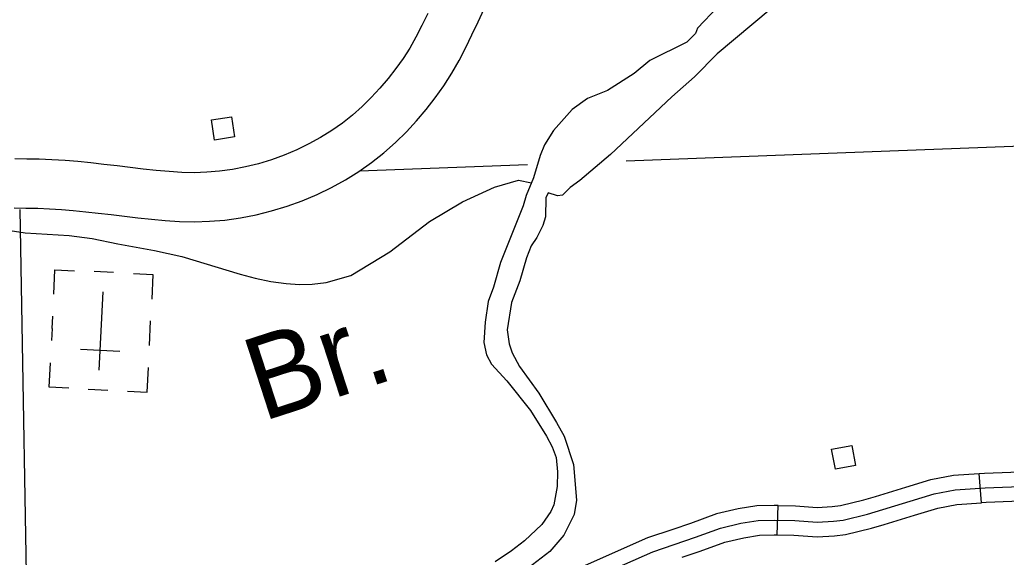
# Model space of a CAD drawing. Extents: x 1370130 to 1380143, y 377636 to 380256.
# Drawn here: x 1377546.5 to 1377687.4, y 378956.8 to 379033.5 of the extents above; entities that cross this region are included whole.
import ezdxf

# ---------------------------------------------------------------- set-up
doc = ezdxf.new("R2010")
doc.units = 0
for name, color, linetype in [('Level 15', 7, 'Continuous'), ('Level 31', 7, 'Continuous'), ('Level 35', 7, 'Continuous'), ('Level 5', 7, 'Continuous'), ('Level 56', 7, 'Continuous'), ('Level 57', 7, 'Continuous'), ('Level 6', 7, 'Continuous')]:
    doc.layers.add(name, color=color, linetype=linetype)

msp = doc.modelspace()

# ---------------------------------------------------------------- linework, layer by layer
at = {"layer": 'Level 15'}
msp.add_line((1377547.51, 379013.62), (1377547.51, 379013.62), dxfattribs=at)
for points in [[(1377547.36, 379006.63), (1377549.08, 379006.59), (1377550.76, 379006.54), (1377552.44, 379006.44), (1377554.14, 379006.29), (1377555.91, 379006.11), (1377557.71, 379005.91), (1377559.55, 379005.69), (1377561.44, 379005.46), (1377563.36, 379005.24), (1377565.3, 379005.04), (1377567.27, 379004.86), (1377569.31, 379004.73), (1377571.43, 379004.68), (1377573.59, 379004.74), (1377575.8, 379004.92), (1377578.02, 379005.23), (1377580.24, 379005.66), (1377582.46, 379006.21), (1377584.66, 379006.88), (1377586.83, 379007.66), (1377588.95, 379008.57), (1377591, 379009.57), (1377592.99, 379010.66), (1377594.91, 379011.86), (1377596.74, 379013.15), (1377598.5, 379014.52), (1377600.17, 379016), (1377601.72, 379017.53), (1377603.15, 379019.1), (1377604.52, 379020.69), (1377605.83, 379022.35), (1377607.05, 379024.09), (1377608.18, 379025.88), (1377609.22, 379027.69), (1377610.18, 379029.53), (1377611.07, 379031.36), (1377611.94, 379033.2), (1377612.79, 379035.05)], [(1377604.76, 379034.39), (1377603.93, 379032.68), (1377603.07, 379031.05), (1377602.18, 379029.48), (1377601.23, 379027.98), (1377600.21, 379026.54), (1377599.11, 379025.13), (1377597.92, 379023.75), (1377596.67, 379022.39), (1377595.38, 379021.11), (1377594.02, 379019.91), (1377592.57, 379018.77), (1377591.04, 379017.7), (1377589.44, 379016.7), (1377587.78, 379015.78), (1377586.04, 379014.94), (1377584.26, 379014.18), (1377582.44, 379013.52), (1377580.59, 379012.96), (1377578.73, 379012.49), (1377576.87, 379012.13), (1377575.03, 379011.88), (1377573.21, 379011.73), (1377571.41, 379011.68), (1377569.62, 379011.72), (1377567.81, 379011.84), (1377565.97, 379012.01), (1377564.12, 379012.2), (1377562.26, 379012.41), (1377560.39, 379012.64), (1377558.51, 379012.86), (1377556.65, 379013.07), (1377554.8, 379013.26), (1377552.96, 379013.42), (1377551.08, 379013.53), (1377549.25, 379013.59), (1377547.51, 379013.62)], [(1377547.51, 379013.62), (1377545.78, 379013.66)], [(1377545.67, 379006.66), (1377547.36, 379006.63)]]:
    msp.add_lwpolyline(points, dxfattribs=at)
at = {"layer": 'Level 31'}
for p, q in [((1377683.82, 378964.54), (1377683.52, 378968.73)), ((1377654.67, 378959.97), (1377654.78, 378964.17)), ((1377639.74, 378960.74), (1377639.74, 378960.74))]:
    msp.add_line(p, q, dxfattribs=at)
for points in [[(1377683.52, 378968.73), (1377684.26, 378968.78), (1377690.56, 378969.02), (1377695.81, 378968.94), (1377697.73, 378968.94), (1377698.19, 378969)], [(1377668.7, 378965.46), (1377673.02, 378966.78), (1377676.59, 378967.89), (1377679.82, 378968.47), (1377683.52, 378968.73)], [(1377627.72, 378953.49), (1377636.92, 378957.56), (1377642.98, 378959.63), (1377646.58, 378960.93), (1377649.49, 378961.62), (1377651.95, 378962.01), (1377654.25, 378962.08), (1377657.16, 378962.01), (1377660.38, 378961.78), (1377662.68, 378961.93), (1377664.06, 378962.08), (1377667.58, 378962.93), (1377673.64, 378964.77), (1377677.09, 378965.84), (1377680.08, 378966.38), (1377684.37, 378966.69), (1377690.58, 378966.92)], [(1377654.78, 378964.17), (1377657.26, 378964.11), (1377660.38, 378963.88), (1377662.49, 378964.02), (1377663.7, 378964.16), (1377667.03, 378964.96), (1377668.7, 378965.46)], [(1377698.71, 378964.83), (1377698, 378964.74), (1377695.78, 378964.74), (1377690.61, 378964.82), (1377684.49, 378964.59), (1377683.82, 378964.54)], [(1377654.78, 378964.17), (1377654.24, 378964.18), (1377651.75, 378964.1), (1377649.09, 378963.69), (1377645.98, 378962.95), (1377642.28, 378961.61), (1377639.74, 378960.74)], [(1377669.92, 378961.44), (1377674.26, 378962.76), (1377677.59, 378963.8), (1377680.34, 378964.29), (1377683.82, 378964.54)], [(1377639.74, 378960.74), (1377636.16, 378959.52), (1377626.81, 378955.39), (1377625.84, 378954.88)], [(1377654.67, 378959.97), (1377657.06, 378959.91), (1377660.37, 378959.67), (1377662.86, 378959.84), (1377664.42, 378960.01), (1377668.14, 378960.9), (1377669.92, 378961.44)], [(1377641.1, 378956.77), (1377643.68, 378957.65), (1377647.18, 378958.92), (1377649.9, 378959.56), (1377652.14, 378959.91), (1377654.25, 378959.98), (1377654.67, 378959.97)]]:
    msp.add_lwpolyline(points, dxfattribs=at)
at = {"layer": 'Level 35'}
for points in [[(1377646.19, 379035.38), (1377643.3, 379032.29), (1377642.98, 379031.53), (1377641.74, 379030.32), (1377636.45, 379027.68), (1377634.22, 379025.84), (1377630.42, 379023.43), (1377627.55, 379022.25), (1377625.39, 379020.69), (1377622.72, 379017.72), (1377621.44, 379015.67)], [(1377653.64, 379034.98), (1377646.07, 379028.64), (1377642.85, 379025.38), (1377639.62, 379022.53), (1377630.86, 379014.29), (1377626.49, 379010.55), (1377625.11, 379009.57), (1377624.01, 379008.45), (1377623.28, 379008.35), (1377621.95, 379008.8), (1377621.6, 379008.07), (1377621.57, 379005.37), (1377621.17, 379004.16), (1377620.34, 379002.43), (1377619.52, 379001.23), (1377618.88, 378999.53), (1377617.93, 378996.23), (1377616.71, 378993.12), (1377616.11, 378989.23)], [(1377621.44, 379015.67), (1377620.8, 379014.11), (1377619.88, 379010.95), (1377618.81, 379008.43), (1377618.39, 379006.96), (1377615.13, 378998.84), (1377614.16, 378995.34), (1377613.39, 378993.3), (1377612.97, 378990.32), (1377612.78, 378987.42), (1377613.15, 378985.66), (1377613.85, 378984.33), (1377616.06, 378981.94), (1377619.43, 378977.71), (1377621.73, 378974.06), (1377622.52, 378972.53), (1377623.08, 378971), (1377623.29, 378968.96), (1377623.22, 378966.85), (1377622.74, 378964.26), (1377622.34, 378963.32), (1377621.03, 378961.47), (1377618.58, 378959.12), (1377616.72, 378957.68), (1377614.4, 378956.11)], [(1377599.36, 379000.4), (1377605, 379004.73), (1377609.7, 379007.54), (1377614.29, 379009.62), (1377617.7, 379010.62), (1377619.59, 379010.21)], [(1377498.18, 379003.48), (1377504.89, 379003.32), (1377510.78, 379003.45), (1377527.96, 379004.26), (1377532.34, 379004.24), (1377538.62, 379003.89), (1377541.99, 379003.88), (1377547.27, 379003.08), (1377553.54, 379002.7), (1377556.83, 379002.26), (1377560.49, 379001.52), (1377565.74, 379000.55), (1377569.63, 378999.72), (1377577.97, 378997.17), (1377580.12, 378996.62), (1377582.35, 378996.14), (1377584.54, 378995.87), (1377586.46, 378995.72), (1377588.26, 378995.76), (1377590.25, 378995.99), (1377593.79, 378997), (1377599.36, 379000.4)], [(1377616.11, 378989.23), (1377616.4, 378987.22), (1377616.79, 378985.97), (1377617.87, 378984), (1377620.62, 378980.18), (1377623.15, 378976.02), (1377624.23, 378974.06), (1377625.55, 378970.01), (1377625.99, 378964.94), (1377625.69, 378962.89), (1377624.18, 378959.91), (1377622.18, 378957.6), (1377619.11, 378955.23)]]:
    msp.add_lwpolyline(points, dxfattribs=at)
at = {"layer": 'Level 5'}
for points in [[(1377633.11, 379013.36), (1377694.59, 379015.69)], [(1377595.01, 379011.93), (1377619.02, 379012.83)]]:
    msp.add_lwpolyline(points, dxfattribs=at)
at = {"layer": 'Level 56'}
for points in [[(1377576.74, 379019.67), (1377577.18, 379016.79), (1377574.29, 379016.34), (1377573.85, 379019.22)], [(1377665.31, 378972.75), (1377665.86, 378969.89), (1377662.99, 378969.34), (1377662.44, 378972.2)]]:
    msp.add_lwpolyline(points, close=True, dxfattribs=at)
at = {"layer": 'Level 57'}
for p, q in [((1377559.9, 378997.41), (1377557.1, 378997.55)), ((1377557.83, 378983.49), (1377558.38, 378994.68)), ((1377551.11, 378989.43), (1377551.2, 378991.2)), ((1377565.01, 378987.02), (1377565.18, 378990.52)), ((1377551.11, 378989.43), (1377551.03, 378987.7)), ((1377558.1, 378989.09), (1377558.1, 378989.09)), ((1377558.1, 378989.09), (1377558.1, 378989.09)), ((1377560.77, 378986.15), (1377555.15, 378986.43)), ((1377556.28, 378980.77), (1377559.08, 378980.63))]:
    msp.add_line(p, q, dxfattribs=at)
for points in [[(1377551.35, 378994.32), (1377551.52, 378997.82), (1377554.32, 378997.68)], [(1377562.71, 378997.27), (1377565.5, 378997.14), (1377565.33, 378993.64)], [(1377553.5, 378980.9), (1377550.71, 378981.04), (1377550.88, 378984.53)], [(1377561.89, 378980.49), (1377564.69, 378980.36), (1377564.86, 378983.85)]]:
    msp.add_lwpolyline(points, dxfattribs=at)
at = {"layer": 'Level 6'}
msp.add_lwpolyline([(1377546.52, 379006.41), (1377547.67, 378937.99), (1377584.62, 378938.81), (1377584.88, 378922.65)], dxfattribs=at)

# ---------------------------------------------------------------- texts
at = {"layer": 'Level 35'}
msp.add_text('Br.', height=11.827, rotation=17.9866, dxfattribs=at).set_placement((1377581.12, 378976.11))

doc.saveas('drawing.dxf')
